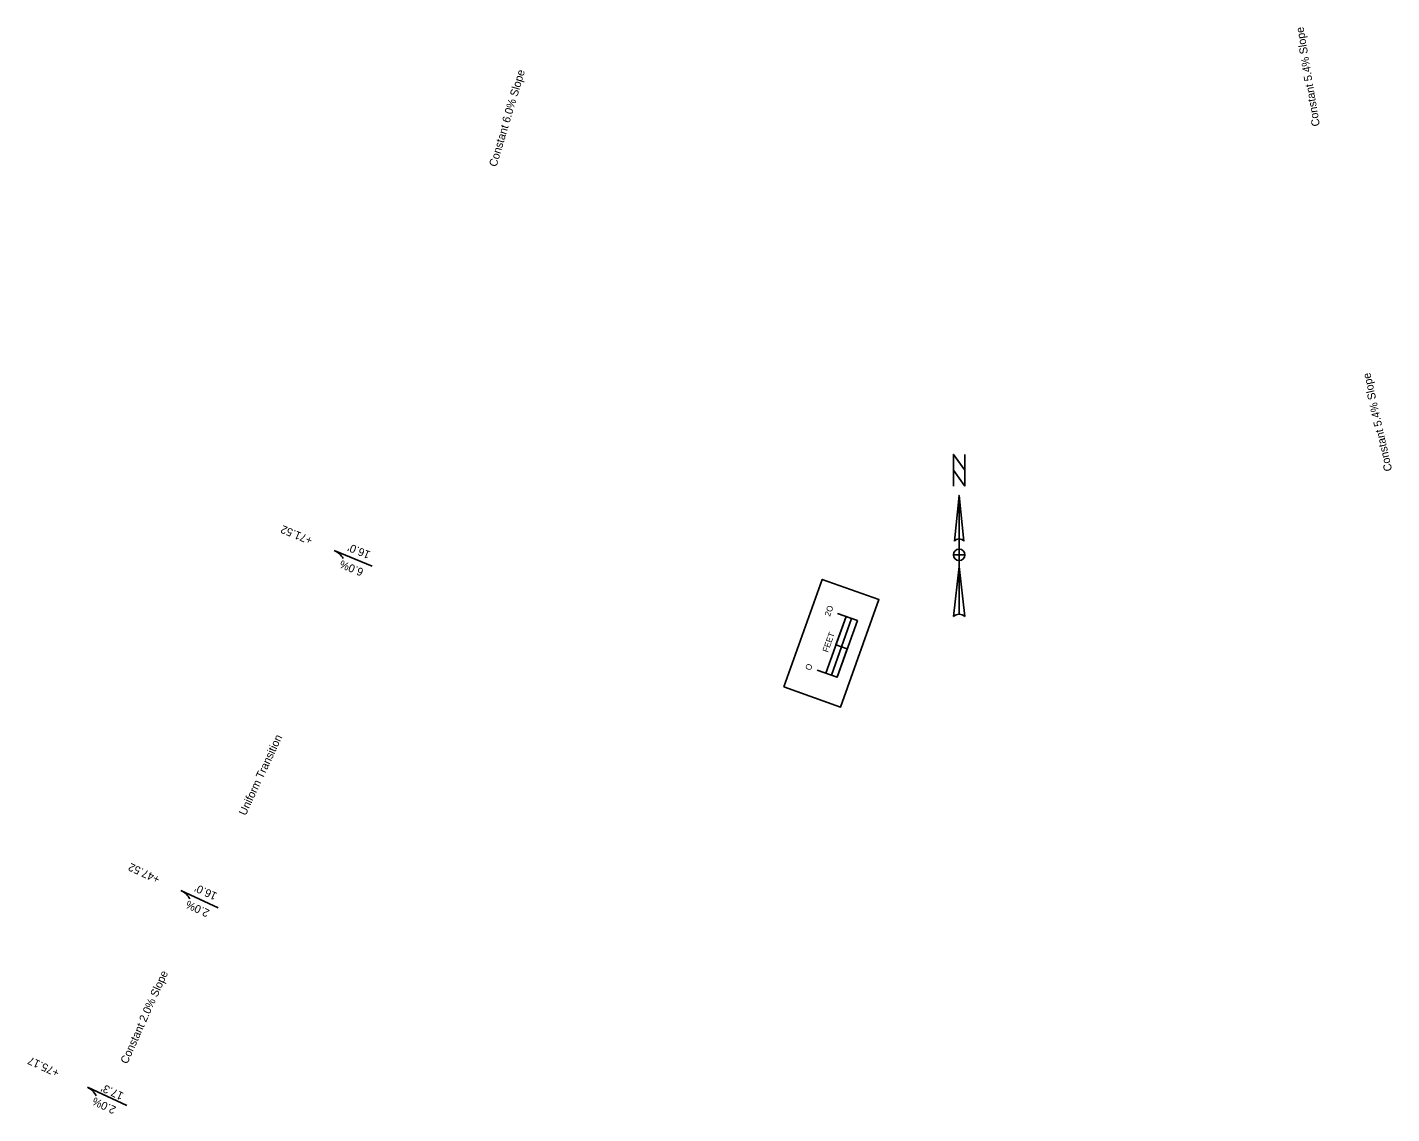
# Model space of a CAD drawing. Extents: x 20506035 to 20507470, y 7969245 to 7972296.
# Drawn here: x 20506360.1 to 20506814.1, y 7971201.1 to 7971562.6 of the extents above; entities that cross this region are included whole.
import ezdxf

# ---------------------------------------------------------------- set-up
doc = ezdxf.new("R2010")
doc.units = 0
doc.layers.add('_CIVIL_CONSTRUCTION', color=7, linetype='Continuous')
doc.layers.add('EdgeShoulder', color=7, linetype='Continuous')

msp = doc.modelspace()

# ---------------------------------------------------------------- linework, layer by layer
at = {"layer": '_CIVIL_CONSTRUCTION'}
for p, q in [((20506462.21, 7971388.5), (20506474.83, 7971383.3)), ((20506632.95, 7971355.75), (20506629.18, 7971357.1)), ((20506632.95, 7971355.75), (20506629.18, 7971357.1)), ((20506411.23, 7971275.39), (20506423.62, 7971269.65)), ((20506380.13, 7971209.88), (20506393.26, 7971203.8))]:
    msp.add_line(p, q, dxfattribs=at)
for points in [[(20506611.87, 7971343.1), (20506624.64, 7971378.89), (20506643.47, 7971372.17), (20506630.71, 7971336.38)], [(20506611.87, 7971343.1), (20506624.64, 7971378.89), (20506643.47, 7971372.17), (20506630.71, 7971336.38)], [(20506631.05, 7971356.43), (20506634.41, 7971365.85), (20506632.54, 7971366.51), (20506629.18, 7971357.1)], [(20506629.59, 7971346.33), (20506632.95, 7971355.75), (20506631.05, 7971356.43), (20506627.69, 7971347.01)]]:
    msp.add_lwpolyline(points, close=True, dxfattribs=at)
for points in [[(20506622.99, 7971348.69), (20506629.59, 7971346.33), (20506636.31, 7971365.17), (20506629.71, 7971367.52)], [(20506625.82, 7971347.68), (20506632.54, 7971366.51)]]:
    msp.add_lwpolyline(points, dxfattribs=at)
for centre, start, end in [((20506459.86, 7971382.8), 29.4323, 67.583), ((20506408.63, 7971269.8), 26.9813, 65.132), ((20506377.53, 7971204.29), 26.9813, 65.132)]:
    msp.add_arc(centre, 6.16, start, end, dxfattribs=at)
at = {"layer": 'EdgeShoulder'}
for p, q in [((20506670.19, 7971406.82), (20506671.71, 7971391.61)), ((20506670.19, 7971406.82), (20506670.19, 7971367.27)), ((20506668.67, 7971391.61), (20506668.67, 7971391.61)), ((20506668.73, 7971391.75), (20506669.01, 7971392.07)), ((20506668.29, 7971366.51), (20506670.19, 7971383.24)), ((20506670.19, 7971385.15), (20506670.19, 7971385.15))]:
    msp.add_line(p, q, dxfattribs=at)
msp.add_lwpolyline([(20506672.09, 7971409.87), (20506668.29, 7971415.19), (20506668.29, 7971420.51), (20506672.09, 7971415.19)], close=True, dxfattribs=at)
for points in [[(20506668.29, 7971409.87), (20506668.29, 7971420.51), (20506672.09, 7971415.19), (20506672.09, 7971420.51)], [(20506668.67, 7971391.61), (20506670.19, 7971406.82), (20506670.19, 7971392.37)], [(20506670.19, 7971385.15), (20506670.19, 7971387.05), (20506668.29, 7971387.05)], [(20506672.09, 7971387.05), (20506670.19, 7971387.05), (20506670.19, 7971388.95)], [(20506670.19, 7971367.27), (20506670.19, 7971383.24), (20506672.09, 7971366.51)]]:
    msp.add_lwpolyline(points, dxfattribs=at)
for centre, radius, start, end in [((20506670.19, 7971390.47), 1.9, 90.0204, 143.1257), ((20506670.19, 7971390.47), 1.9, 36.8481, 90.0218), ((20506670.19, 7971387.05), 1.9, 90, 180), ((20506670.19, 7971387.05), 1.9, 180, 270), ((20506670.19, 7971387.05), 1.9, 0, 90), ((20506670.19, 7971387.05), 1.9, 270, 360), ((20506670.19, 7971364.52), 2.76, 89.9894, 133.619), ((20506670.19, 7971364.51), 2.76, 46.4021, 90.0006)]:
    msp.add_arc(centre, radius, start, end, dxfattribs=at)

# ---------------------------------------------------------------- texts
at = {"layer": '_CIVIL_CONSTRUCTION'}
for s, height, rotation, p in [('Constant 5.4% Slope', 2.664, 99.3877, (20506790.25, 7971529.88)), ('Constant 6.0% Slope', 2.664, 73.4346, (20506516.2, 7971516)), ('Constant 5.4% Slope', 2.664, 102.6559, (20506814.33, 7971415.18)), ('+71.52', 2.664, 157.6091, (20506455.27, 7971392.8)), ("16.0'", 2.664, 157.7118, (20506474.48, 7971388.06)), ('6.0%', 2.664, 157.7118, (20506472.21, 7971382.31)), ('2O', 2, 70.3655, (20506627.2, 7971366.43)), ('FEET', 2, 70.3655, (20506626.53, 7971354.44)), ('O', 2, 70.3655, (20506620.78, 7971348.43)), ('Uniform Transition', 2.664, 65.1011, (20506432.75, 7971300.1)), ('+47.52', 2.664, 155.1581, (20506404.48, 7971279.98)), ("16.0'", 2.664, 155.2608, (20506423.47, 7971274.42)), ('2.0%', 2.664, 155.2608, (20506420.95, 7971268.77)), ('Constant 2.0% Slope', 2.664, 65.9216, (20506393.36, 7971217.44)), ('+75.17', 2.664, 155.1581, (20506371.01, 7971215.57)), ("17.3'", 2.664, 155.2608, (20506392.35, 7971207.91)), ('2.0%', 2.664, 155.2608, (20506389.85, 7971203.27))]:
    msp.add_text(s, height=height, rotation=rotation, dxfattribs=at).set_placement(p)

doc.saveas('drawing.dxf')
